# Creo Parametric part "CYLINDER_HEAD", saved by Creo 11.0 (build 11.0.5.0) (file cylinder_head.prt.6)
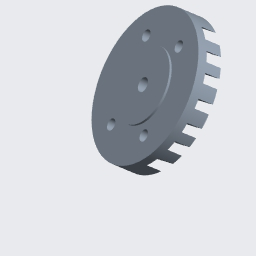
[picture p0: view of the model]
Materials in the file: 10038_S235JR

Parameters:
  MATERIAL = "10038_S235JR"
  PTC_MATERIAL_NAME = "10038_S235JR"
  PTC_MASTER_MATERIAL = "10038_S235JR"
  SELECT_EN_NAME = "S235JR"
  SELECT_DIN_NAME = "RSt37-2"
  SELECT_MATERIAL_NUMBER = "1.0038"
  SELECT_ASTM_NAME = "A 283 M Grade 2"
  MATERIAL_GROUP = "ME_ST_Baustahl"
  STANDARD_EN_DELIVERYSPEC = "DIN EN 10025-2"
  STANDARD_DIN_DELIVERYSPEC = "DIN EN 10025-2"

Other parameters: GEWICHT

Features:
  1. datum plane "RIGHT"
  2. datum plane "TOP"
  3. datum plane "FRONT"
  4. coordinate system
  5. datum axis
  6. datum axis
  7. datum axis
  8. revolve "Revolve 1"
  9. pattern "Pattern 1"
  10. extruded cut "Extrude 1"
  11. extruded cut "Extrude 1 [2]"
  12. extruded cut "Extrude 1 [3]"
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
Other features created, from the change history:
  mirror "Mirror 1"
  pattern "Pattern 1 (2)"
  extruded cut "Extrude 1 (2) [1]"
  extruded cut "Extrude 1 (2) [2]"
  extruded cut "Extrude 1 (2) [3]"
  mirror "Mirror 2"
  pattern "Pattern 1 (3)"
  extruded cut "Extrude 1 (3) [1]"
  extruded cut "Extrude 1 (3) [2]"
  extruded cut "Extrude 1 (3) [3]"
  mirror "Mirror 3"
  pattern "Pattern 1 (4)"
  extruded cut "Extrude 1 (4) [1]"
  extruded cut "Extrude 1 (4) [2]"
  extruded cut "Extrude 1 (4) [3]"
  extruded cut "Extrude 2"
  extruded cut "Extrude 3"
  mirror "Mirror 4"
  extruded cut "Extrude 3 (2)"
  mirror "Mirror 5"
  extruded cut "Extrude 3 (3)"
  mirror "Mirror 6"
  extruded cut "Extrude 3 (4)"
  extruded cut "Extrude 4"
  extruded cut "Extrude 5"
  mirror "Mirror 7"
  extruded cut "Extrude 5 (2)"
  mirror "Mirror 8"
  extruded cut "Extrude 5 (3)"
  mirror "Mirror 9"
  extruded cut "Extrude 5 (4)"
  extruded cut "Extrude 1 [4]" (2 times)
  extruded cut "Extrude 1 (2) [4]"
  extruded cut "Extrude 1 (3) [4]"
  extruded cut "Extrude 1 (4) [4]"
  extruded cut "Extrude 9"
  extruded cut "Extrude 6 [4]"
  extruded cut "Extrude 7 [4]"
  extruded cut "Extrude 8 [4]"
  datum plane "DTM1"
  extrusion "Extrude 9"
  mirror "Mirror 10"
  extruded cut "Extrude 9 (2)"
  extrusion "Extrude 10"
  hole "Hole 1"

Other named items: A_Y, A_X, A_Z, CS0

Layers: BEZUGSACHSEN, BEZUGSEBENEN, BOHRUNGEN

Surfaces: 30 plane, 13 cylinder, 2 cone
